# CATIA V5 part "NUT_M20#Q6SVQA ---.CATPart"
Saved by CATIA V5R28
Part number: NUT_M20#Q6SVPT
Revision: ---
Nomenclature: _
Description: NUT_M20
Property "REP": "CM"
Property "PREF": "Y"
Property "PBS 1": "24"
Property "PBS 2": "CR"
Property "PBS 3": "LC"
Property "DEPT": "_"
Property "DIVN": "_"
Property "GROUP": "_"
Property "UNIT": "_"
Property "PARTY": "_"
Property "RO": "---"
Property "RE": "SEKACHI"
Property "PRO": "---"
Property "Change Type": "Major"
Property "Maturity Level": "CD"
Property "Export Number": "_"
Property "Description Modification": "FDRModel"
Property "Description Documents": "_"
Property "BOM": "_"
Property "AT": "PD"
Property "External Part ID": "_"
Property "LONG": "_"
Property "ID": "Q6SVPT"
Property "User In Enovia": "VAUQUEJ"
Property "Object Type": "_"
Property "CADENAS_ID": "_"
Property "Life Cycle Status": "Approved"
Bounding box of the stored display mesh (mm): x -17.321 to 17.321, y -20 to 20, z -14 to 0
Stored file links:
  C:\Users\pandeym\Desktop\__TCPH\NUT_M20#Q6SVQA ---.CATPart
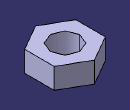
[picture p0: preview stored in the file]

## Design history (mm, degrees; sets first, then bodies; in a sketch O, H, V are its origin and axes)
Body1 (main body)
  Sketch1 on xy-plane, origin (0, 0, 0), H (1, 0, 0), V (0, 1, 0)
    point P1 (17.3205, -10)
    point P2 (17.3205, 10)
    point P3 (0, 20)
    point P4 (-17.3205, 10)
    point P5 (-17.3205, -10)
    point P6 (0, -20)
    point P7 (17.3205, 0)
    line L1 (17.3205, -10) -> (17.3205, 10)
    line L2 (17.3205, 10) -> (0, 20)
    line L3 (0, 20) -> (-17.3205, 10)
    line L4 (-17.3205, 10) -> (-17.3205, -10)
    line L5 (-17.3205, -10) -> (0, -20)
    line L6 (0, -20) -> (17.3205, -10)
    construction line L7 (0, 0) -> (17.3205, 0)
    construction circle A1 centre (0, 0) radius 20
    construction arc A2 centre (-17.3205, -10) radius 20 from (-17.3205, 10) to (0, -20) cw
    construction arc A3 centre (17.3205, 10) radius 20 from (0, 20) to (17.3205, -10) ccw
    circle A4 centre (0, 0) radius 10
    radius A4 = 10
    length L1 = 20
    horizontal: L7 H
    coincidence: A1 P1, A1 P2, A1 P3, A1 P4, A1 P5, A1 P6, A2 O, A3 O
    midpoint: P7 L1
    parallelism: L1 L4
  Pad1: profile Sketch1, direction (0, 0, -1), length 14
